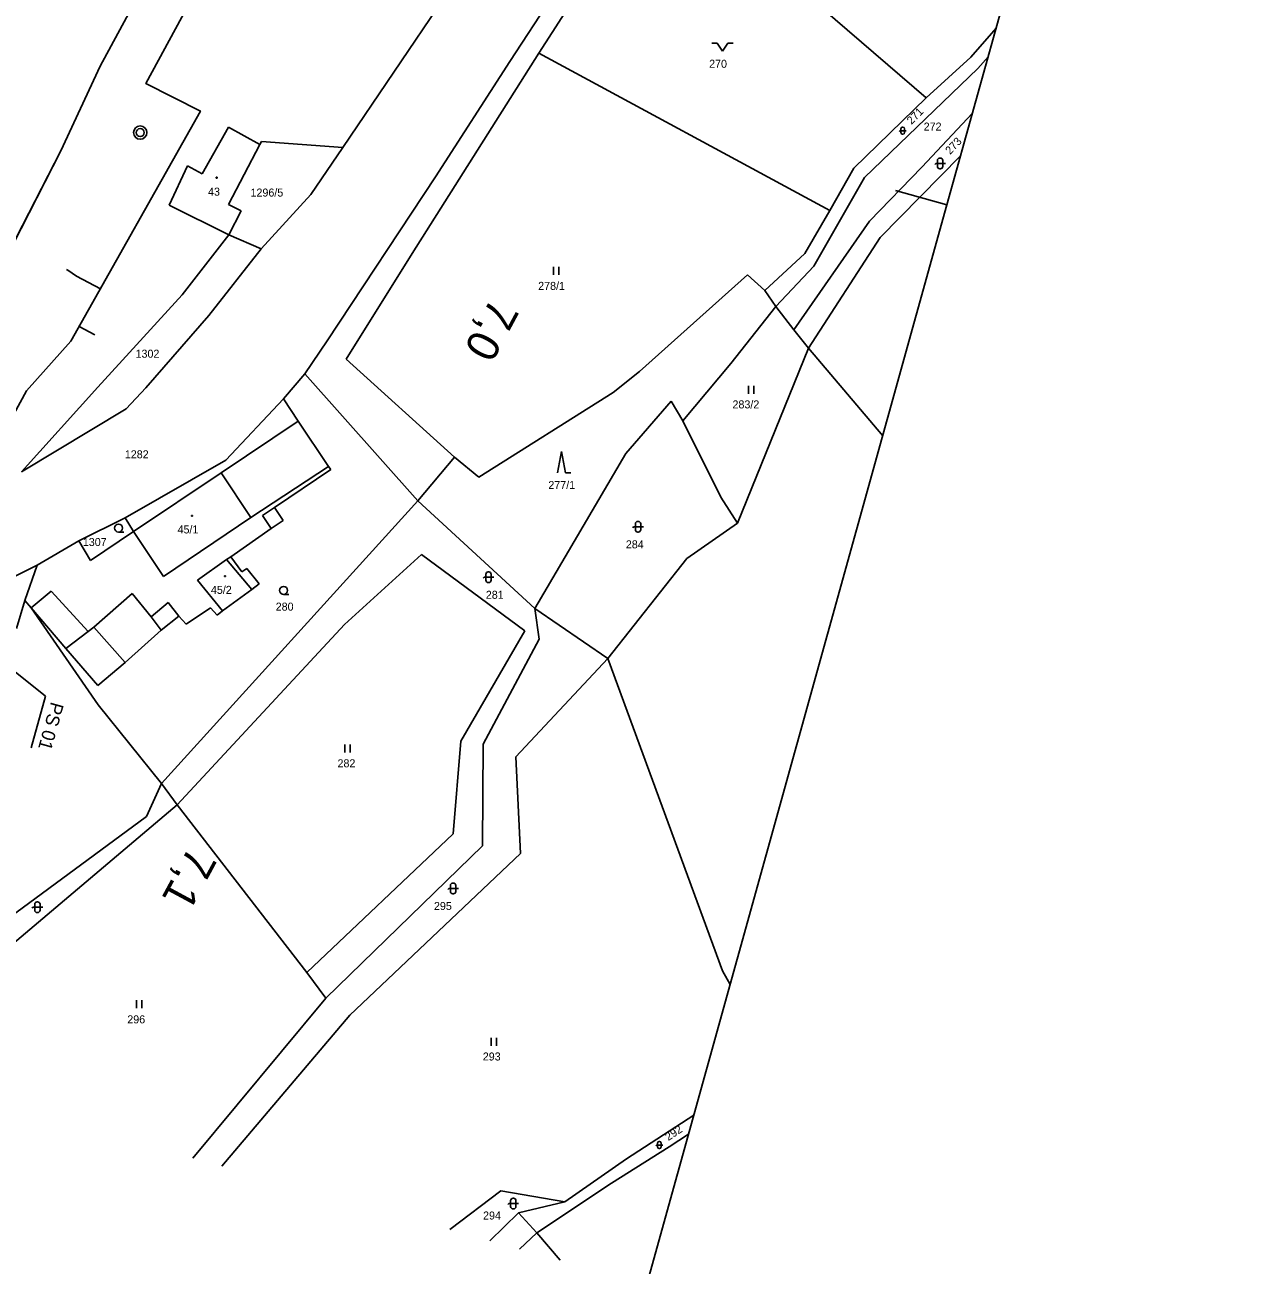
# Model space of a CAD drawing. Extents: x -795094 to -794639, y -1135368 to -1134681.
# Drawn here: x -794868.2 to -794639.2, y -1135161.8 to -1134929.4 of the extents above; entities that cross this region are included whole.
import ezdxf

# ---------------------------------------------------------------- set-up
doc = ezdxf.new("R2010")
doc.units = 0
for name, color, linetype in [('Default', 7, 'Continuous'), ('formát', 7, 'Continuous'), ('kilometráž - vrstava 7', 7, 'Continuous'), ('kn_celek - Cisla pozemkovych parcel', 7, 'Continuous'), ('kn_celek - Cisla stavebnich parcel', 7, 'Continuous'), ('kn_celek - Hranice parcel', 7, 'Continuous'), ('kn_celek - Vnitrni kresby', 7, 'Continuous'), ('kn_celek - Znacky budov', 7, 'Continuous'), ('kn_celek - Znacky kultur', 7, 'Continuous'), ('plochy - SZDC', 7, 'Continuous'), ('PSR_C2_1_trasa_Strunkovice - Kabelová trasa', 7, 'Continuous'), ('SOPS', 7, 'Continuous')]:
    doc.layers.add(name, color=color, linetype=linetype)

# ---------------------------------------------------------------- blocks, each defined once
blk = doc.blocks.new('701')
at = {"layer": 'Default'}
for p, q in [((-20, 15), (-10, 15)), ((-10, 15), (0, 0)), ((0, 0), (10, 15)), ((10, 15), (20, 15))]:
    blk.add_line(p, q, dxfattribs=at)
blk = doc.blocks.new('316')
at = {"layer": 'Default'}
for p, q in [((-8.3, 10), (-10, 8.1)), ((-5, 10), (-8.3, 10)), ((-5, 15.5), (-5, 4.5)), ((-5, 10), (5, 10)), ((0.5, 20), (-0.5, 20)), ((-0.5, 0), (0.5, 0)), ((5, 4.5), (5, 15.5)), ((10, 10), (5, 10))]:
    blk.add_line(p, q, dxfattribs=at)
for centre, start, end in [((-0.5, 15.5), 90, 180), ((-0.5, 4.5), 180, 270), ((0.5, 15.5), 0, 90), ((0.5, 4.5), 270, 0)]:
    blk.add_arc(centre, 4.5, start, end, dxfattribs=at)
blk = doc.blocks.new('308')
at = {"layer": 'Default'}
for p, q in [((-7.5, 0.2), (0, 40.2)), ((0, 40.2), (7.5, 0.2)), ((7.5, 0.2), (17.5, 0.2))]:
    blk.add_line(p, q, dxfattribs=at)
blk = doc.blocks.new('306')
at = {"layer": 'Default'}
for p, q in [((-5.2, 0), (-5.2, 15)), ((4.8, 0), (4.8, 15))]:
    blk.add_line(p, q, dxfattribs=at)
blk = doc.blocks.new('304')
at = {"layer": 'Default'}
blk.add_line((-0.1, 0), (9.9, 0), dxfattribs=at)
blk.add_circle((-0.1, 7.5), 7.5, dxfattribs=at)
blk = doc.blocks.new('402')
at = {"layer": 'Default'}
for p, q in [((-0.8, 0.8), (0.7, 0.8)), ((-0.8, 0.8), (-0.8, -0.7)), ((0.7, 0.8), (0.7, -0.7)), ((0.7, -0.7), (-0.8, -0.7))]:
    blk.add_line(p, q, dxfattribs=at)

msp = doc.modelspace()

# ---------------------------------------------------------------- linework, layer by layer
at = {"layer": 'formát'}
for p, q in [((-794639.16, -1134760.77), (-794695.41, -1134963.1)), ((-794705.05, -1134960.42), (-794695.41, -1134963.1)), ((-794705.05, -1134960.42), (-794695.41, -1134963.1)), ((-794695.41, -1134963.1), (-794751.67, -1135165.42))]:
    msp.add_line(p, q, dxfattribs=at)
at = {"layer": 'kilometráž - vrstava 7'}
for radius in [1.25, 0.752]:
    msp.add_circle((-794846.58, -1134949.57), radius, dxfattribs=at)
at = {"layer": 'kn_celek - Hranice parcel'}
for p, q in [((-794808.62, -1134952.39), (-794771.93, -1134898.11)), ((-794834.03, -1134899.62), (-794854.06, -1134937.12)), ((-794777.33, -1134936.24), (-794754.68, -1134901.67)), ((-794753.41, -1134906.1), (-794771.9, -1134934.67)), ((-794721.7, -1134923.76), (-794699.33, -1134943.07)), ((-794690.95, -1134935.41), (-794686.21, -1134929.99)), ((-794771.9, -1134934.67), (-794795.64, -1134972.22)), ((-794771.9, -1134934.67), (-794717.38, -1134964.18)), ((-794699.33, -1134943.07), (-794690.95, -1134935.41)), ((-794687.7, -1134935.35), (-794689.6, -1134937.57)), ((-794861.46, -1134953), (-794854.06, -1134937.12)), ((-794791.22, -1134957.88), (-794777.33, -1134936.24)), ((-794689.6, -1134937.57), (-794710.84, -1134957.99)), ((-794712.86, -1134956.24), (-794699.33, -1134943.07)), ((-794700.14, -1134956.07), (-794690.63, -1134945.9)), ((-794830.05, -1134948.55), (-794835, -1134957.3)), ((-794824.17, -1134951.78), (-794830.05, -1134948.55)), ((-794830.03, -1134963.03), (-794824.17, -1134951.78)), ((-794823.88, -1134951.22), (-794824.17, -1134951.78)), ((-794808.62, -1134952.39), (-794823.88, -1134951.22)), ((-794880.53, -1134990.11), (-794861.46, -1134953)), ((-794814.63, -1134961.17), (-794808.62, -1134952.39)), ((-794707.96, -1134969.21), (-794692.9, -1134953.94)), ((-794692.9, -1134953.94), (-794692.85, -1134953.88)), ((-794837.72, -1134955.82), (-794841.15, -1134963.17)), ((-794835, -1134957.3), (-794837.72, -1134955.82)), ((-794717.38, -1134964.18), (-794712.86, -1134956.24)), ((-794709.96, -1134966.19), (-794700.14, -1134956.07)), ((-794811.54, -1134988.57), (-794791.22, -1134957.88)), ((-794710.84, -1134957.99), (-794720.33, -1134974.63)), ((-794841.15, -1134963.17), (-794829.96, -1134968.76)), ((-794827.67, -1134964.22), (-794830.03, -1134963.03)), ((-794823.89, -1134971.38), (-794814.63, -1134961.17)), ((-794829.96, -1134968.76), (-794827.67, -1134964.22)), ((-794722.07, -1134972.22), (-794717.38, -1134964.18)), ((-794724.09, -1134986.54), (-794709.96, -1134966.19)), ((-794838.74, -1134979.98), (-794829.96, -1134968.76)), ((-794829.96, -1134968.76), (-794823.89, -1134971.38)), ((-794721.35, -1134989.98), (-794707.96, -1134969.21)), ((-794833.74, -1134983.85), (-794823.89, -1134971.38)), ((-794795.64, -1134972.22), (-794807.97, -1134992.03)), ((-794729.53, -1134979.17), (-794722.07, -1134972.22)), ((-794720.33, -1134974.63), (-794727.46, -1134982.14)), ((-794732.81, -1134976.22), (-794753.01, -1134994.34)), ((-794732.81, -1134976.22), (-794729.53, -1134979.17)), ((-794727.46, -1134982.14), (-794729.53, -1134979.17)), ((-794854.54, -1134997.31), (-794838.74, -1134979.98)), ((-794845.54, -1134997.39), (-794833.74, -1134983.85)), ((-794735.92, -1134992.86), (-794727.46, -1134982.14)), ((-794727.46, -1134982.14), (-794724.09, -1134986.54)), ((-794721.35, -1134989.98), (-794724.09, -1134986.54)), ((-794815.72, -1134994.78), (-794811.54, -1134988.57)), ((-794734.68, -1135022.74), (-794721.35, -1134989.98)), ((-794721.35, -1134989.98), (-794707.45, -1135006.4)), ((-794807.97, -1134992.03), (-794787.66, -1135010.39)), ((-794744.91, -1135003.61), (-794735.92, -1134992.86)), ((-794819.75, -1134999.49), (-794815.72, -1134994.78)), ((-794794.56, -1135018.59), (-794815.72, -1134994.78)), ((-794757.97, -1134998.25), (-794753.01, -1134994.34)), ((-794868.85, -1135013.13), (-794854.54, -1134997.31)), ((-794849.21, -1135001.34), (-794845.54, -1134997.39)), ((-794783.1, -1135014.17), (-794757.97, -1134998.25)), ((-794830.56, -1135010.99), (-794819.75, -1134999.49)), ((-794819.75, -1134999.49), (-794816.96, -1135003.65)), ((-794755.58, -1135009.68), (-794747.11, -1134999.89)), ((-794747.11, -1134999.89), (-794744.91, -1135003.61)), ((-794868.85, -1135013.13), (-794849.21, -1135001.34)), ((-794816.96, -1135003.65), (-794811.28, -1135012.12)), ((-794737.76, -1135017.88), (-794744.91, -1135003.61)), ((-794772.66, -1135038.78), (-794755.58, -1135009.68)), ((-794849.37, -1135021.74), (-794830.56, -1135010.99)), ((-794811.28, -1135012.12), (-794810.89, -1135012.7)), ((-794787.66, -1135010.39), (-794794.56, -1135018.59)), ((-794783.1, -1135014.17), (-794787.66, -1135010.39)), ((-794810.89, -1135012.7), (-794821.41, -1135019.83)), ((-794794.56, -1135018.59), (-794842.62, -1135071.54)), ((-794794.56, -1135018.59), (-794772.66, -1135038.78)), ((-794734.68, -1135022.74), (-794737.76, -1135017.88)), ((-794821.41, -1135019.83), (-794819.8, -1135022.24)), ((-794858.08, -1135026.1), (-794849.37, -1135021.74)), ((-794847.86, -1135024.36), (-794849.37, -1135021.74)), ((-794822.04, -1135023.74), (-794829.62, -1135029.07)), ((-794819.8, -1135022.24), (-794822.04, -1135023.74)), ((-794734.68, -1135022.74), (-794744.17, -1135029.42)), ((-794865.9, -1135030.62), (-794858.08, -1135026.1)), ((-794858.08, -1135026.1), (-794855.92, -1135029.76)), ((-794855.92, -1135029.76), (-794847.86, -1135024.36)), ((-794871, -1135033.19), (-794865.9, -1135030.62)), ((-794868.19, -1135037.26), (-794865.9, -1135030.62)), ((-794835.85, -1135033.45), (-794830.41, -1135029.59)), ((-794830.41, -1135029.59), (-794829.62, -1135029.07)), ((-794829.62, -1135029.07), (-794827.54, -1135031.87)), ((-794808.32, -1135041.79), (-794793.87, -1135028.67)), ((-794793.87, -1135028.67), (-794774.51, -1135042.94)), ((-794744.17, -1135029.42), (-794758.97, -1135048.16)), ((-794827.54, -1135031.87), (-794826.62, -1135031.27)), ((-794826.62, -1135031.27), (-794824.3, -1135034.12)), ((-794831.13, -1135039.21), (-794835.85, -1135033.45)), ((-794825.68, -1135035.22), (-794831.13, -1135039.21)), ((-794824.3, -1135034.12), (-794825.68, -1135035.22)), ((-794868.19, -1135037.26), (-794869.73, -1135042.52)), ((-794867.01, -1135038.66), (-794868.19, -1135037.26)), ((-794854.46, -1135056.79), (-794867.01, -1135038.66)), ((-794860.51, -1135046.26), (-794867.01, -1135038.66)), ((-794833.41, -1135038.61), (-794837.95, -1135041.71)), ((-794832.13, -1135039.98), (-794833.41, -1135038.61)), ((-794831.13, -1135039.21), (-794832.13, -1135039.98)), ((-794758.97, -1135048.16), (-794772.66, -1135038.78)), ((-794771.83, -1135044.52), (-794772.66, -1135038.78)), ((-794839.35, -1135040.2), (-794842.66, -1135042.84)), ((-794839.63, -1135075.55), (-794808.32, -1135041.79)), ((-794837.95, -1135041.71), (-794839.35, -1135040.2)), ((-794842.66, -1135042.84), (-794849.37, -1135048.87)), ((-794774.51, -1135042.94), (-794786.48, -1135063.64)), ((-794782.32, -1135064.21), (-794771.83, -1135044.52)), ((-794854.55, -1135053.18), (-794860.51, -1135046.26)), ((-794849.37, -1135048.87), (-794854.55, -1135053.18)), ((-794758.97, -1135048.16), (-794776.2, -1135066.57)), ((-794758.97, -1135048.16), (-794737.47, -1135106.65)), ((-794842.62, -1135071.54), (-794854.46, -1135056.79)), ((-794786.48, -1135063.64), (-794787.97, -1135081.01)), ((-794782.45, -1135083.24), (-794782.32, -1135064.21)), ((-794776.2, -1135066.57), (-794775.33, -1135084.68)), ((-794845.43, -1135077.77), (-794842.62, -1135071.54)), ((-794842.62, -1135071.54), (-794839.63, -1135075.55)), ((-794871.31, -1135102.33), (-794839.63, -1135075.55)), ((-794839.63, -1135075.55), (-794815.34, -1135106.98)), ((-794873.86, -1135098.71), (-794845.43, -1135077.77)), ((-794787.97, -1135081.01), (-794815.34, -1135106.98)), ((-794811.81, -1135111.77), (-794782.45, -1135083.24)), ((-794775.33, -1135084.68), (-794807.29, -1135115)), ((-794815.34, -1135106.98), (-794811.81, -1135111.77)), ((-794737.47, -1135106.65), (-794736.04, -1135109.22)), ((-794836.71, -1135141.78), (-794811.81, -1135111.77)), ((-794807.29, -1135115), (-794831.26, -1135143.29)), ((-794755.44, -1135141.92), (-794742.84, -1135133.69)), ((-794747.48, -1135139.63), (-794743.84, -1135137.26)), ((-794758.26, -1135146.49), (-794747.48, -1135139.63)), ((-794767.01, -1135149.93), (-794755.44, -1135141.92)), ((-794772.25, -1135155.74), (-794758.26, -1135146.49)), ((-794788.57, -1135155.16), (-794779.02, -1135147.89)), ((-794779.02, -1135147.89), (-794767.01, -1135149.93)), ((-794767.01, -1135149.93), (-794775.69, -1135152)), ((-794781.07, -1135157.25), (-794775.69, -1135152)), ((-794775.69, -1135152), (-794772.25, -1135155.74)), ((-794775.48, -1135158.8), (-794772.25, -1135155.74)), ((-794772.25, -1135155.74), (-794767.86, -1135160.92))]:
    msp.add_line(p, q, dxfattribs=at)
at = {"layer": 'kn_celek - Vnitrni kresby'}
for p, q in [((-794831.41, -1135013.34), (-794816.96, -1135003.65)), ((-794825.82, -1135021.69), (-794811.28, -1135012.12)), ((-794831.41, -1135013.34), (-794847.86, -1135024.36)), ((-794825.82, -1135021.69), (-794831.41, -1135013.34)), ((-794823.65, -1135021.33), (-794821.41, -1135019.83)), ((-794823.65, -1135021.33), (-794822.04, -1135023.74)), ((-794842.24, -1135032.75), (-794825.82, -1135021.69)), ((-794847.86, -1135024.36), (-794842.24, -1135032.75)), ((-794830.41, -1135029.59), (-794825.68, -1135035.22)), ((-794867.01, -1135038.66), (-794863.24, -1135035.51)), ((-794863.24, -1135035.51), (-794856.31, -1135043.04)), ((-794855.27, -1135042.25), (-794848.09, -1135035.98)), ((-794848.09, -1135035.98), (-794844.51, -1135040.3)), ((-794844.51, -1135040.3), (-794841.31, -1135037.66)), ((-794841.31, -1135037.66), (-794839.35, -1135040.2)), ((-794856.31, -1135043.04), (-794855.27, -1135042.25)), ((-794855.27, -1135042.25), (-794849.37, -1135048.87)), ((-794844.51, -1135040.3), (-794842.66, -1135042.84)), ((-794860.51, -1135046.26), (-794856.31, -1135043.04))]:
    msp.add_line(p, q, dxfattribs=at)
at = {"layer": 'plochy - SZDC'}
for p, q in [((-794808.62, -1134952.39), (-794771.93, -1134898.11)), ((-794834.03, -1134899.62), (-794854.06, -1134937.12)), ((-794854.06, -1134937.12), (-794861.46, -1134953)), ((-794835, -1134957.3), (-794830.05, -1134948.55)), ((-794830.05, -1134948.55), (-794824.17, -1134951.78)), ((-794824.17, -1134951.78), (-794823.88, -1134951.22)), ((-794823.88, -1134951.22), (-794808.62, -1134952.39)), ((-794861.46, -1134953), (-794880.53, -1134990.11)), ((-794841.15, -1134963.17), (-794837.72, -1134955.82)), ((-794837.72, -1134955.82), (-794835, -1134957.3)), ((-794829.96, -1134968.76), (-794841.15, -1134963.17)), ((-794838.74, -1134979.98), (-794829.96, -1134968.76)), ((-794854.54, -1134997.31), (-794838.74, -1134979.98)), ((-794868.85, -1135013.13), (-794854.54, -1134997.31))]:
    msp.add_line(p, q, dxfattribs=at)
at = {"layer": 'PSR_C2_1_trasa_Strunkovice - Kabelová trasa'}
for p, q in [((-794855.08, -1134987.47), (-794858.01, -1134985.89)), ((-794859.57, -1134988.66), (-794867.89, -1134997.98)), ((-794867.89, -1134997.98), (-794877.13, -1135014.95))]:
    msp.add_line(p, q, dxfattribs=at)
for points in [[(-794859.57, -1134988.66), (-794835.3, -1134945.55), (-794845.51, -1134940.37), (-794776.44, -1134813), (-794772.18, -1134815.08)], [(-794860.41, -1134975.21), (-794860.15, -1134975.35), (-794858.49, -1134976.45), (-794854.05, -1134978.87)]]:
    msp.add_lwpolyline(points, dxfattribs=at)
at = {"layer": 'SOPS'}
for p, q in [((-794888.21, -1135036.13), (-794864.32, -1135055.18)), ((-794864.32, -1135055.18), (-794867.02, -1135064.88))]:
    msp.add_line(p, q, dxfattribs=at)

# ---------------------------------------------------------------- block references
at = {"layer": 'kn_celek - Znacky budov', "xscale": 0.1, "yscale": 0.10000000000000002}
for p in [(-794832.25, -1134958.03), (-794836.86, -1135021.4), (-794830.69, -1135032.69)]:
    msp.add_blockref('402', p, dxfattribs=at)
at = {"layer": 'kn_celek - Znacky kultur'}
for name, p, xscale, yscale in [('701', (-794737.45, -1134934.31), 0.1, 0.10000000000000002), ('316', (-794703.7, -1134949.88), 0.067, 0.067), ('316', (-794696.7, -1134956.35), 0.1, 0.10000000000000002), ('306', (-794768.59, -1134976.24), 0.1, 0.10000000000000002), ('306', (-794732.1, -1134998.54), 0.1, 0.10000000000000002), ('308', (-794767.62, -1135013.35), 0.1, 0.10000000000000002), ('304', (-794850.63, -1135024.43), 0.1, 0.10000000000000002), ('316', (-794753.3, -1135024.44), 0.1, 0.10000000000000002), ('316', (-794781.32, -1135033.9), 0.1, 0.10000000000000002), ('304', (-794819.7, -1135036.12), 0.1, 0.10000000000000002), ('306', (-794807.72, -1135065.72), 0.1, 0.10000000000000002), ('316', (-794787.95, -1135092.23), 0.1, 0.10000000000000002), ('316', (-794865.85, -1135095.74), 0.1, 0.10000000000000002), ('306', (-794846.77, -1135113.68), 0.1, 0.10000000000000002), ('306', (-794780.27, -1135120.7), 0.1, 0.10000000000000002), ('316', (-794749.31, -1135139.98), 0.067, 0.067), ('316', (-794776.67, -1135151.28), 0.1, 0.10000000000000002)]:
    msp.add_blockref(name, p, dxfattribs=dict(at, xscale=xscale, yscale=yscale))

# ---------------------------------------------------------------- texts
at = {"layer": 'kilometráž - vrstava 7'}
for s, rotation, p in [('7,0', 241.6619, (-794780.73, -1134980.29)), ('7,1', 241.6466, (-794837.35, -1135083.14))]:
    msp.add_text(s, height=6, rotation=rotation, dxfattribs=at).set_placement(p)
at = {"layer": 'kn_celek - Cisla pozemkovych parcel'}
for s, p in [('270', (-794739.98, -1134937.42)), ('272', (-794699.78, -1134949.19)), ('1296/5', (-794825.91, -1134961.56)), ('278/1', (-794772.01, -1134979.05)), ('1302', (-794847.45, -1134991.76)), ('283/2', (-794735.6, -1135001.26)), ('1282', (-794849.46, -1135010.61)), ('277/1', (-794770.11, -1135016.37)), ('1307', (-794857.33, -1135027.05)), ('284', (-794755.58, -1135027.49)), ('281', (-794781.82, -1135036.94)), ('280', (-794821.19, -1135039.16)), ('282', (-794809.61, -1135068.52)), ('295', (-794791.54, -1135095.26)), ('296', (-794849, -1135116.51)), ('293', (-794782.39, -1135123.47)), ('294', (-794782.34, -1135153.27))]:
    msp.add_text(s, height=1.5, dxfattribs=at).set_placement(p)
for s, rotation, p in [('271', 45.339, (-794702.05, -1134948.15)), ('273', 46.7562, (-794694.81, -1134953.76)), ('292', 33.3794, (-794747.62, -1135138.57))]:
    msp.add_text(s, height=1.5, rotation=rotation, dxfattribs=at).set_placement(p)
at = {"layer": 'kn_celek - Cisla stavebnich parcel'}
for s, p in [('43', (-794833.87, -1134961.39)), ('45/1', (-794839.58, -1135024.69)), ('45/2', (-794833.33, -1135036.02))]:
    msp.add_text(s, height=1.5, dxfattribs=at).set_placement(p)
at = {"layer": 'SOPS'}
msp.add_text('PS 01', height=2.5, rotation=254.4625, dxfattribs=at).set_placement((-794863.28, -1135056.13))

doc.saveas('drawing.dxf')
